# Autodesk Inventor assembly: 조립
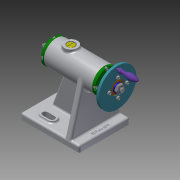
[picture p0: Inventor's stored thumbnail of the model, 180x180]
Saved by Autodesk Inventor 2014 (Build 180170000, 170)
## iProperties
Created: 2019-10
Part Number: 조립
Document SubType Name: Assembly
Designer: kh
Author: kh
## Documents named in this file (18)
- C:\Users\kh\Desktop\491004V1042\조립.iam
- C:\Users\kh\Desktop\491004V1042\본체.ipt
- C:\Users\kh\Desktop\491004V1042\나사.ipt
- C:\Users\kh\Desktop\491004V1042\나사축.ipt
- C:\Users\kh\Desktop\491004V1042\너트 M8.ipt
- C:\Users\kh\Desktop\491004V1042\돌림판.ipt
- C:\Users\kh\Desktop\491004V1042\멈춤나사 M3.ipt
- C:\Users\kh\Desktop\491004V1042\볼트 M3.ipt
- C:\Users\kh\Desktop\491004V1042\부시.ipt
- C:\Users\kh\Desktop\491004V1042\센터.ipt
- C:\Users\kh\Desktop\491004V1042\센터홀더.ipt
- C:\Users\kh\Desktop\491004V1042\슬리브.ipt
- C:\Users\kh\Desktop\491004V1042\와셔.ipt
- C:\Users\kh\Desktop\491004V1042\중공축.ipt
- C:\Users\kh\Desktop\491004V1042\커버.ipt
- C:\Users\kh\Desktop\491004V1042\키 4 x 4 x 10.ipt
- C:\Users\kh\Desktop\491004V1042\플랜지.ipt
- C:\Users\kh\Desktop\491004V1042\핸들.ipt
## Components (2 placed, 2 different names)
1. 플랜지:1 — Mate:23, Mate:24, Mate:25, Insert:3, Mate:26, Mate:30
2. 핸들:1 — Mate:33, Flush:4
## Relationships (8: Mate 6, Insert 1, Flush 1)
- Mate:23: 플랜지:1
- Mate:24: 플랜지:1
- Mate:25: 플랜지:1
- Insert:3: 플랜지:1
- Mate:26: 플랜지:1
- Mate:30: 플랜지:1
- Mate:33: 핸들:1
- Flush:4: 핸들:1
